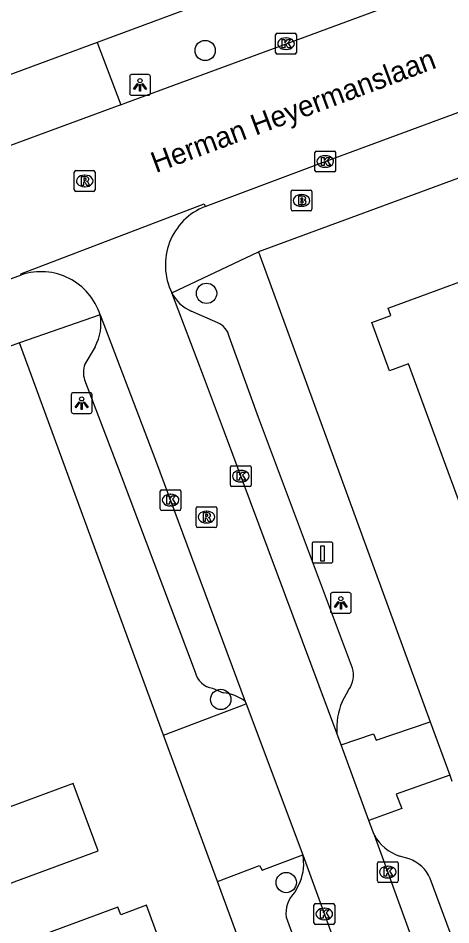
# Model space of a CAD drawing. Extents: x 161258 to 161838, y 380836 to 381727.
# Drawn here: x 161610.91 to 161631.75, y 381428.59 to 381472.25 of the extents above; entities that cross this region are included whole.
import ezdxf

# ---------------------------------------------------------------- set-up
doc = ezdxf.new("R2010")
doc.units = 0
for name, color, linetype in [('IMGEO_Boom', 7, 'Continuous'), ('IMGEO_Brandkraan', 7, 'Continuous'), ('IMGEO_Kolk', 7, 'Continuous'), ('IMGEO_Laadpaal', 7, 'Continuous'), ('IMGEO_Lichtpunt', 7, 'Continuous'), ('IMGEO_Openbare_ruimte_label', 7, 'Continuous'), ('IMGEO_Pand', 7, 'Continuous'), ('IMGEO_Rijbaan_lokaal_open', 7, 'Continuous'), ('IMGEO_Rioolput', 7, 'Continuous'), ('IMGEO_Voetpad_open', 7, 'Continuous')]:
    doc.layers.add(name, color=color, linetype=linetype)

msp = doc.modelspace()

# ---------------------------------------------------------------- linework, layer by layer
at = {"layer": 'IMGEO_Boom'}
for centre in [(161619.92, 381470.692), (161619.985, 381458.999), (161620.669, 381439.444), (161623.822, 381430.63)]:
    msp.add_circle(centre, 0.489, dxfattribs=at)
at = {"layer": 'IMGEO_Brandkraan'}
for p, q in [((161624.136, 381463.971), (161624.988, 381463.971)), ((161624.061, 381463.045), (161624.061, 381463.897)), ((161624.549, 381463.751), (161624.574, 381463.751)), ((161625.062, 381463.897), (161625.062, 381463.045)), ((161624.572, 381463.191), (161624.547, 381463.191)), ((161624.988, 381462.971), (161624.136, 381462.971))]:
    msp.add_line(p, q, dxfattribs=at)
for points in [[(161624.136, 381463.971), (161624.988, 381463.971)], [(161624.061, 381463.045), (161624.061, 381463.897)], [(161624.409, 381463.671), (161624.409, 381463.271), (161624.622, 381463.271)], [(161624.64, 381463.671), (161624.409, 381463.671)], [(161624.588, 381463.59), (161624.534, 381463.59), (161624.534, 381463.514)], [(161624.534, 381463.514), (161624.587, 381463.514)], [(161625.062, 381463.897), (161625.062, 381463.045)], [(161624.596, 381463.438), (161624.534, 381463.438), (161624.534, 381463.357)], [(161624.534, 381463.357), (161624.596, 381463.357)], [(161624.988, 381462.971), (161624.136, 381462.971)]]:
    msp.add_lwpolyline(points, dxfattribs=at)
for centre, radius, start, end in [((161624.138, 381463.895), 0.0765, 91.552, 178.448), ((161624.138, 381463.895), 0.0765, 91.552, 178.448), ((161624.986, 381463.895), 0.0765, 1.552, 88.448), ((161624.986, 381463.895), 0.0765, 1.552, 88.448), ((161624.589, 381463.552), 0.0379, 267.8285, 90.9355), ((161624.644, 381463.526), 0.145, 59.4692, 91.5367), ((161624.669, 381463.573), 0.0922, 285.5137, 58.1501), ((161624.597, 381463.397), 0.0404, 269.8759, 90.5077), ((161624.628, 381463.522), 0.251, 268.6676, 293.5347), ((161624.674, 381463.381), 0.105, 301.3115, 78.989), ((161624.138, 381463.047), 0.0765, 181.552, 268.448), ((161624.138, 381463.047), 0.0765, 181.552, 268.448), ((161624.986, 381463.047), 0.0765, 271.552, 358.448), ((161624.986, 381463.047), 0.0765, 271.552, 358.448)]:
    msp.add_arc(centre, radius, start, end, dxfattribs=at)
for centre, major_axis, ratio, start_param, end_param in [((161624.548, 381463.471), (-0.387, 0.002), 0.722429, 4.712389, 7.853982), ((161624.573, 381463.471), (-0.39, 0.002), 0.717154, 1.570796, 4.712389)]:
    msp.add_ellipse(centre, major_axis=major_axis, ratio=ratio, start_param=start_param, end_param=end_param, dxfattribs=at)
at = {"layer": 'IMGEO_Kolk'}
for p, q in [((161623.313, 381470.594), (161623.313, 381471.446)), ((161623.388, 381471.52), (161624.24, 381471.52)), ((161624.314, 381471.446), (161624.314, 381470.594)), ((161623.801, 381471.3), (161623.826, 381471.3)), ((161624.24, 381470.52), (161623.388, 381470.52)), ((161623.824, 381470.74), (161623.799, 381470.74)), ((161625.202, 381464.921), (161625.202, 381465.773)), ((161625.277, 381465.847), (161626.129, 381465.847)), ((161626.203, 381465.773), (161626.203, 381464.921)), ((161625.69, 381465.627), (161625.715, 381465.627)), ((161626.129, 381464.847), (161625.277, 381464.847)), ((161625.713, 381465.067), (161625.688, 381465.067)), ((161621.133, 381449.77), (161621.133, 381450.622)), ((161621.208, 381450.696), (161622.06, 381450.696)), ((161621.621, 381450.476), (161621.646, 381450.476)), ((161622.134, 381450.622), (161622.134, 381449.77)), ((161617.83, 381449.544), (161618.682, 381449.544)), ((161622.06, 381449.696), (161621.208, 381449.696)), ((161621.644, 381449.916), (161621.619, 381449.916)), ((161617.755, 381448.618), (161617.755, 381449.47)), ((161618.243, 381449.324), (161618.268, 381449.324)), ((161618.756, 381449.47), (161618.756, 381448.618)), ((161618.266, 381448.764), (161618.241, 381448.764)), ((161618.682, 381448.544), (161617.83, 381448.544)), ((161628.285, 381431.633), (161629.137, 381431.633)), ((161628.21, 381430.707), (161628.21, 381431.559)), ((161628.698, 381431.413), (161628.723, 381431.413)), ((161629.211, 381431.559), (161629.211, 381430.707)), ((161628.721, 381430.853), (161628.696, 381430.853)), ((161629.137, 381430.633), (161628.285, 381430.633)), ((161625.156, 381428.69), (161625.156, 381429.542)), ((161625.231, 381429.616), (161626.083, 381429.616)), ((161626.157, 381429.542), (161626.157, 381428.69)), ((161625.644, 381429.396), (161625.669, 381429.396)), ((161626.083, 381428.616), (161625.231, 381428.616)), ((161625.667, 381428.836), (161625.642, 381428.836))]:
    msp.add_line(p, q, dxfattribs=at)
for points in [[(161623.313, 381470.594), (161623.313, 381471.446)], [(161623.388, 381471.52), (161624.24, 381471.52)], [(161624.314, 381471.446), (161624.314, 381470.594)], [(161623.634, 381471.22), (161623.757, 381471.22), (161623.757, 381471.069), (161623.887, 381471.22), (161624.051, 381471.22), (161623.905, 381471.069), (161624.058, 381470.82), (161623.906, 381470.82), (161623.821, 381470.984), (161623.757, 381470.917), (161623.757, 381470.82), (161623.634, 381470.82), (161623.634, 381471.22)], [(161624.24, 381470.52), (161623.388, 381470.52)], [(161625.202, 381464.921), (161625.202, 381465.773)], [(161625.277, 381465.847), (161626.129, 381465.847)], [(161626.203, 381465.773), (161626.203, 381464.921)], [(161625.523, 381465.547), (161625.646, 381465.547), (161625.646, 381465.396), (161625.776, 381465.547), (161625.94, 381465.547), (161625.794, 381465.396), (161625.947, 381465.147), (161625.795, 381465.147), (161625.71, 381465.311), (161625.646, 381465.244), (161625.646, 381465.147), (161625.523, 381465.147), (161625.523, 381465.547)], [(161626.129, 381464.847), (161625.277, 381464.847)], [(161621.133, 381449.77), (161621.133, 381450.622)], [(161621.208, 381450.696), (161622.06, 381450.696)], [(161621.454, 381450.396), (161621.577, 381450.396), (161621.577, 381450.245), (161621.707, 381450.396), (161621.871, 381450.396), (161621.725, 381450.245), (161621.878, 381449.996), (161621.726, 381449.996), (161621.641, 381450.16), (161621.577, 381450.093), (161621.577, 381449.996), (161621.454, 381449.996), (161621.454, 381450.396)], [(161622.134, 381450.622), (161622.134, 381449.77)], [(161617.83, 381449.544), (161618.682, 381449.544)], [(161622.06, 381449.696), (161621.208, 381449.696)], [(161617.755, 381448.618), (161617.755, 381449.47)], [(161618.076, 381449.244), (161618.199, 381449.244), (161618.199, 381449.093), (161618.329, 381449.244), (161618.493, 381449.244), (161618.347, 381449.093), (161618.5, 381448.844), (161618.348, 381448.844), (161618.263, 381449.008), (161618.199, 381448.941), (161618.199, 381448.844), (161618.076, 381448.844), (161618.076, 381449.244)], [(161618.756, 381449.47), (161618.756, 381448.618)], [(161618.682, 381448.544), (161617.83, 381448.544)], [(161628.285, 381431.633), (161629.137, 381431.633)], [(161628.21, 381430.707), (161628.21, 381431.559)], [(161628.531, 381431.333), (161628.654, 381431.333), (161628.654, 381431.182), (161628.784, 381431.333), (161628.948, 381431.333), (161628.802, 381431.182), (161628.955, 381430.933), (161628.803, 381430.933), (161628.718, 381431.097), (161628.654, 381431.03), (161628.654, 381430.933), (161628.531, 381430.933), (161628.531, 381431.333)], [(161629.211, 381431.559), (161629.211, 381430.707)], [(161629.137, 381430.633), (161628.285, 381430.633)], [(161625.156, 381428.69), (161625.156, 381429.542)], [(161625.231, 381429.616), (161626.083, 381429.616)], [(161626.157, 381429.542), (161626.157, 381428.69)], [(161625.477, 381429.316), (161625.6, 381429.316), (161625.6, 381429.165), (161625.73, 381429.316), (161625.894, 381429.316), (161625.748, 381429.165), (161625.901, 381428.916), (161625.749, 381428.916), (161625.664, 381429.08), (161625.6, 381429.013), (161625.6, 381428.916), (161625.477, 381428.916), (161625.477, 381429.316)], [(161626.083, 381428.616), (161625.231, 381428.616)]]:
    msp.add_lwpolyline(points, dxfattribs=at)
for centre, start, end in [((161623.39, 381471.444), 91.552, 178.448), ((161623.39, 381471.444), 91.552, 178.448), ((161624.238, 381471.444), 1.552, 88.448), ((161624.238, 381471.444), 1.552, 88.448), ((161623.39, 381470.596), 181.552, 268.448), ((161623.39, 381470.596), 181.552, 268.448), ((161624.238, 381470.596), 271.552, 358.448), ((161624.238, 381470.596), 271.552, 358.448), ((161625.279, 381465.771), 91.552, 178.448), ((161625.279, 381465.771), 91.552, 178.448), ((161626.127, 381465.771), 1.552, 88.448), ((161626.127, 381465.771), 1.552, 88.448), ((161625.279, 381464.923), 181.552, 268.448), ((161625.279, 381464.923), 181.552, 268.448), ((161626.127, 381464.923), 271.552, 358.448), ((161626.127, 381464.923), 271.552, 358.448), ((161621.21, 381450.62), 91.552, 178.448), ((161621.21, 381450.62), 91.552, 178.448), ((161622.058, 381450.62), 1.552, 88.448), ((161622.058, 381450.62), 1.552, 88.448), ((161617.832, 381449.468), 91.552, 178.448), ((161617.832, 381449.468), 91.552, 178.448), ((161618.68, 381449.468), 1.552, 88.448), ((161618.68, 381449.468), 1.552, 88.448), ((161621.21, 381449.772), 181.552, 268.448), ((161621.21, 381449.772), 181.552, 268.448), ((161622.058, 381449.772), 271.552, 358.448), ((161622.058, 381449.772), 271.552, 358.448), ((161617.832, 381448.62), 181.552, 268.448), ((161617.832, 381448.62), 181.552, 268.448), ((161618.68, 381448.62), 271.552, 358.448), ((161618.68, 381448.62), 271.552, 358.448), ((161628.287, 381431.557), 91.552, 178.448), ((161628.287, 381431.557), 91.552, 178.448), ((161629.135, 381431.557), 1.552, 88.448), ((161629.135, 381431.557), 1.552, 88.448), ((161628.287, 381430.709), 181.552, 268.448), ((161628.287, 381430.709), 181.552, 268.448), ((161629.135, 381430.709), 271.552, 358.448), ((161629.135, 381430.709), 271.552, 358.448), ((161625.233, 381429.54), 91.552, 178.448), ((161625.233, 381429.54), 91.552, 178.448), ((161626.081, 381429.54), 1.552, 88.448), ((161626.081, 381429.54), 1.552, 88.448), ((161625.233, 381428.692), 181.552, 268.448), ((161625.233, 381428.692), 181.552, 268.448), ((161626.081, 381428.692), 271.552, 358.448), ((161626.081, 381428.692), 271.552, 358.448)]:
    msp.add_arc(centre, 0.0765, start, end, dxfattribs=at)
for centre, major_axis, ratio, start_param, end_param in [((161623.8, 381471.02), (-0.387, 0.002), 0.722429, 4.712389, 7.853982), ((161623.825, 381471.02), (-0.39, 0.002), 0.717154, 1.570796, 4.712389), ((161625.689, 381465.347), (-0.387, 0.002), 0.722429, 4.712389, 7.853982), ((161625.714, 381465.347), (-0.39, 0.002), 0.717154, 1.570796, 4.712389), ((161621.62, 381450.196), (-0.387, 0.002), 0.722429, 4.712389, 7.853982), ((161621.645, 381450.196), (-0.39, 0.002), 0.717154, 1.570796, 4.712389), ((161618.242, 381449.044), (-0.387, 0.002), 0.722429, 4.712389, 7.853982), ((161618.267, 381449.044), (-0.39, 0.002), 0.717154, 1.570796, 4.712389), ((161628.697, 381431.133), (-0.387, 0.002), 0.722429, 4.712389, 7.853982), ((161628.722, 381431.133), (-0.39, 0.002), 0.717154, 1.570796, 4.712389), ((161625.643, 381429.116), (-0.387, 0.002), 0.722429, 4.712389, 7.853982), ((161625.668, 381429.116), (-0.39, 0.002), 0.717154, 1.570796, 4.712389)]:
    msp.add_ellipse(centre, major_axis=major_axis, ratio=ratio, start_param=start_param, end_param=end_param, dxfattribs=at)
at = {"layer": 'IMGEO_Laadpaal'}
for p, q in [((161625.069, 381446.938), (161625.069, 381446.097)), ((161625.069, 381446.938), (161625.069, 381446.097)), ((161625.985, 381447.022), (161625.144, 381447.022)), ((161625.985, 381447.022), (161625.144, 381447.022)), ((161626.069, 381446.106), (161626.069, 381446.947)), ((161626.069, 381446.106), (161626.069, 381446.947)), ((161625.153, 381446.022), (161625.994, 381446.022)), ((161625.153, 381446.022), (161625.994, 381446.022))]:
    msp.add_line(p, q, dxfattribs=at)
msp.add_lwpolyline([(161625.484, 381446.835), (161625.644, 381446.835), (161625.644, 381446.102), (161625.484, 381446.102), (161625.484, 381446.835)], dxfattribs=at)
for centre, start, end in [((161625.147, 381446.944), 92.4484, 184.2845), ((161625.147, 381446.944), 92.4484, 184.2845), ((161625.991, 381446.944), 2.4484, 94.2845), ((161625.991, 381446.944), 2.4484, 94.2845), ((161625.147, 381446.1), 182.4484, 274.2845), ((161625.147, 381446.1), 182.4484, 274.2845), ((161625.991, 381446.1), 272.4484, 4.2845), ((161625.991, 381446.1), 272.4484, 4.2845)]:
    msp.add_arc(centre, 0.0779, start, end, dxfattribs=at)
at = {"layer": 'IMGEO_Lichtpunt'}
for p, q in [((161616.285, 381469.441), (161616.285, 381468.634)), ((161616.285, 381469.441), (161616.285, 381468.634)), ((161617.187, 381469.536), (161616.379, 381469.536)), ((161617.187, 381469.536), (161616.379, 381469.536)), ((161617.281, 381468.634), (161617.281, 381469.441)), ((161617.281, 381468.634), (161617.281, 381469.441)), ((161616.379, 381468.54), (161617.187, 381468.54)), ((161616.379, 381468.54), (161617.187, 381468.54)), ((161613.476, 381454.118), (161613.476, 381453.311)), ((161613.476, 381454.118), (161613.476, 381453.311)), ((161614.378, 381454.213), (161613.57, 381454.213)), ((161614.378, 381454.213), (161613.57, 381454.213)), ((161614.472, 381453.311), (161614.472, 381454.118)), ((161614.472, 381453.311), (161614.472, 381454.118)), ((161613.57, 381453.217), (161614.378, 381453.217)), ((161613.57, 381453.217), (161614.378, 381453.217)), ((161625.954, 381444.499), (161625.954, 381443.692)), ((161625.954, 381444.499), (161625.954, 381443.692)), ((161626.856, 381444.594), (161626.048, 381444.594)), ((161626.856, 381444.594), (161626.048, 381444.594)), ((161626.95, 381443.692), (161626.95, 381444.499)), ((161626.95, 381443.692), (161626.95, 381444.499)), ((161626.048, 381443.598), (161626.856, 381443.598)), ((161626.048, 381443.598), (161626.856, 381443.598))]:
    msp.add_line(p, q, dxfattribs=at)
for points in [[(161616.659, 381469.105), (161616.698, 381469.077), (161616.51, 381468.815), (161616.472, 381468.842), (161616.659, 381469.105)], [(161616.761, 381469.057), (161616.808, 381469.057), (161616.808, 381468.735), (161616.761, 381468.735), (161616.761, 381469.057)], [(161616.871, 381469.077), (161616.909, 381469.104), (161617.096, 381468.842), (161617.057, 381468.814), (161616.871, 381469.077)], [(161613.85, 381453.782), (161613.889, 381453.754), (161613.701, 381453.492), (161613.663, 381453.519), (161613.85, 381453.782)], [(161613.952, 381453.734), (161613.999, 381453.734), (161613.999, 381453.412), (161613.952, 381453.412), (161613.952, 381453.734)], [(161614.062, 381453.754), (161614.1, 381453.781), (161614.287, 381453.519), (161614.248, 381453.491), (161614.062, 381453.754)], [(161626.328, 381444.163), (161626.367, 381444.135), (161626.179, 381443.873), (161626.141, 381443.9), (161626.328, 381444.163)], [(161626.43, 381444.115), (161626.477, 381444.115), (161626.477, 381443.793), (161626.43, 381443.793), (161626.43, 381444.115)], [(161626.54, 381444.135), (161626.578, 381444.162), (161626.765, 381443.9), (161626.726, 381443.872), (161626.54, 381444.135)]]:
    msp.add_lwpolyline(points, dxfattribs=at)
for centre in [(161616.784, 381469.239), (161613.975, 381453.916), (161626.453, 381444.297)]:
    msp.add_circle(centre, 0.0994, dxfattribs=at)
for centre, start, end in [((161616.379, 381469.441), 90, 180), ((161616.379, 381469.441), 90, 180), ((161617.187, 381469.441), 0, 90), ((161617.187, 381469.441), 0, 90), ((161616.379, 381468.634), 180, 270), ((161616.379, 381468.634), 180, 270), ((161617.187, 381468.634), 270, 0), ((161617.187, 381468.634), 270, 360), ((161613.57, 381454.118), 90, 180), ((161613.57, 381454.118), 90, 180), ((161614.378, 381454.118), 0, 90), ((161614.378, 381454.118), 0, 90), ((161613.57, 381453.311), 180, 270), ((161613.57, 381453.311), 180, 270), ((161614.378, 381453.311), 270, 0), ((161614.378, 381453.311), 270, 360), ((161626.048, 381444.499), 90, 180), ((161626.048, 381444.499), 90, 180), ((161626.856, 381444.499), 0, 90), ((161626.856, 381444.499), 0, 90), ((161626.048, 381443.692), 180, 270), ((161626.048, 381443.692), 180, 270), ((161626.856, 381443.692), 270, 0), ((161626.856, 381443.692), 270, 360)]:
    msp.add_arc(centre, 0.0946, start, end, dxfattribs=at)
at = {"layer": 'IMGEO_Pand'}
for points in [[(161638.75, 381449.971), (161639.816, 381447.073), (161637.103, 381446.076), (161635.232, 381445.389), (161633.679, 381444.818), (161633.593, 381445.054), (161632.008, 381449.363), (161631.512, 381450.712), (161629.712, 381455.604), (161628.803, 381455.27), (161627.947, 381457.598), (161628.856, 381457.932), (161628.725, 381458.288), (161634.845, 381460.539)], [(161606.966, 381429.283), (161614.764, 381432.159), (161613.568, 381435.402), (161605.743, 381432.515)], [(161618.756, 381423.997), (161617.959, 381426.177), (161618.288, 381426.298), (161617.095, 381429.532), (161615.858, 381429.075), (161615.722, 381429.445), (161611.031, 381427.715), (161607.245, 381426.324), (161608.439, 381423.08), (161607.73, 381422.818), (161607.88, 381422.411), (161606.945, 381422.066), (161607.734, 381419.929), (161609.375, 381420.535)]]:
    msp.add_lwpolyline(points, dxfattribs=at)
at = {"layer": 'IMGEO_Rijbaan_lokaal_open'}
for points in [[(161615.861, 381468.083), (161616.105, 381468.173), (161623.814, 381471.02), (161647.71, 381479.843), (161654.992, 381482.542)], [(161619.919, 381463.183), (161625.703, 381465.347), (161649.734, 381474.239), (161657.089, 381476.959)], [(161615.861, 381468.083), (161607.479, 381464.988)], [(161611.076, 381459.891), (161611.051, 381459.932), (161619.88, 381463.313), (161619.919, 381463.183)], [(161589.036, 381451.805), (161590.467, 381452.331), (161605.602, 381457.905), (161611.076, 381459.891)], [(161626.262, 381437.814), (161620.858, 381452.321), (161619.845, 381455.009), (161618.312, 381459.03)], [(161614.862, 381457.971), (161617.533, 381450.961), (161621.851, 381439.353)], [(161621.851, 381439.353), (161621.897, 381439.229)], [(161621.897, 381439.229), (161624.621, 381431.971)], [(161626.464, 381437.265), (161626.262, 381437.814)], [(161627.799, 381433.622), (161626.464, 381437.265)], [(161628.071, 381432.908), (161628.007, 381433.055), (161627.799, 381433.622)], [(161633.562, 381417.932), (161631.642, 381423.104), (161628.071, 381432.908)], [(161624.621, 381431.971), (161629.58, 381418.332)]]:
    msp.add_lwpolyline(points, dxfattribs=at)
for centre, radius, start, end in [((161621.036, 381460.364), 3.033, 111.605, 206.0871), ((161612.014, 381457.048), 2.994, 17.9573, 108.2607)]:
    msp.add_arc(centre, radius, start, end, dxfattribs=at)
at = {"layer": 'IMGEO_Rioolput'}
for p, q in [((161613.62, 381463.985), (161613.62, 381464.837)), ((161613.695, 381464.911), (161614.547, 381464.911)), ((161614.621, 381464.837), (161614.621, 381463.985)), ((161614.108, 381464.691), (161614.133, 381464.691)), ((161614.131, 381464.131), (161614.106, 381464.131)), ((161614.547, 381463.911), (161613.695, 381463.911)), ((161619.48, 381447.8), (161619.48, 381448.652)), ((161619.555, 381448.726), (161620.407, 381448.726)), ((161620.481, 381448.652), (161620.481, 381447.8)), ((161619.968, 381448.506), (161619.993, 381448.506)), ((161619.991, 381447.946), (161619.966, 381447.946)), ((161620.407, 381447.726), (161619.555, 381447.726))]:
    msp.add_line(p, q, dxfattribs=at)
for points in [[(161613.62, 381463.985), (161613.62, 381464.837)], [(161613.695, 381464.911), (161614.547, 381464.911)], [(161614.621, 381464.837), (161614.621, 381463.985)], [(161614.209, 381464.609), (161613.957, 381464.611), (161613.957, 381464.211)], [(161613.957, 381464.211), (161614.081, 381464.211), (161614.081, 381464.373), (161614.092, 381464.373)], [(161614.135, 381464.53), (161614.081, 381464.53), (161614.081, 381464.449)], [(161614.081, 381464.449), (161614.133, 381464.449)], [(161614.139, 381464.344), (161614.21, 381464.211), (161614.35, 381464.211), (161614.285, 381464.337)], [(161614.547, 381463.911), (161613.695, 381463.911)], [(161619.48, 381447.8), (161619.48, 381448.652)], [(161619.555, 381448.726), (161620.407, 381448.726)], [(161620.481, 381448.652), (161620.481, 381447.8)], [(161620.069, 381448.424), (161619.817, 381448.426), (161619.817, 381448.026)], [(161619.995, 381448.345), (161619.941, 381448.345), (161619.941, 381448.264)], [(161619.941, 381448.264), (161619.993, 381448.264)], [(161619.817, 381448.026), (161619.941, 381448.026), (161619.941, 381448.188), (161619.952, 381448.188)], [(161619.999, 381448.159), (161620.07, 381448.026), (161620.21, 381448.026), (161620.145, 381448.152)], [(161620.407, 381447.726), (161619.555, 381447.726)]]:
    msp.add_lwpolyline(points, dxfattribs=at)
for centre, radius, start, end in [((161613.697, 381464.835), 0.0765, 91.552, 178.448), ((161613.697, 381464.835), 0.0765, 91.552, 178.448), ((161614.545, 381464.835), 0.0765, 1.552, 88.448), ((161614.545, 381464.835), 0.0765, 1.552, 88.448), ((161614.091, 381464.32), 0.0533, 26.0293, 88.6989), ((161614.117, 381464.638), 0.19, 274.7715, 282.9687), ((161614.141, 381464.434), 0.0964, 77.0061, 93.1865), ((161614.155, 381464.491), 0.0378, 276.6634, 79.6772), ((161614.208, 381464.499), 0.109, 350.3612, 89.416), ((161614.206, 381464.499), 0.112, 277.5842, 350.9817), ((161614.19, 381464.284), 0.108, 29.5134, 73.7905), ((161613.697, 381463.987), 0.0765, 181.552, 268.448), ((161613.697, 381463.987), 0.0765, 181.552, 268.448), ((161614.545, 381463.987), 0.0765, 271.552, 358.448), ((161614.545, 381463.987), 0.0765, 271.552, 358.448), ((161619.557, 381448.65), 0.0765, 91.552, 178.448), ((161619.557, 381448.65), 0.0765, 91.552, 178.448), ((161620.405, 381448.65), 0.0765, 1.552, 88.448), ((161620.405, 381448.65), 0.0765, 1.552, 88.448), ((161619.977, 381448.453), 0.19, 274.7715, 282.9687), ((161620.001, 381448.249), 0.0964, 77.0061, 93.1865), ((161620.015, 381448.306), 0.0378, 276.6634, 79.6772), ((161620.068, 381448.314), 0.109, 350.3612, 89.416), ((161620.066, 381448.314), 0.112, 277.5842, 350.9817), ((161619.557, 381447.802), 0.0765, 181.552, 268.448), ((161619.557, 381447.802), 0.0765, 181.552, 268.448), ((161619.951, 381448.135), 0.0533, 26.0293, 88.6989), ((161620.05, 381448.099), 0.108, 29.5134, 73.7905), ((161620.405, 381447.802), 0.0765, 271.552, 358.448), ((161620.405, 381447.802), 0.0765, 271.552, 358.448)]:
    msp.add_arc(centre, radius, start, end, dxfattribs=at)
for centre, major_axis, ratio, start_param, end_param in [((161614.107, 381464.411), (-0.387, 0.002), 0.722429, 4.712389, 7.853982), ((161614.132, 381464.411), (-0.39, 0.002), 0.717154, 1.570796, 4.712389), ((161619.967, 381448.226), (-0.387, 0.002), 0.722429, 4.712389, 7.853982), ((161619.992, 381448.226), (-0.39, 0.002), 0.717154, 1.570796, 4.712389)]:
    msp.add_ellipse(centre, major_axis=major_axis, ratio=ratio, start_param=start_param, end_param=end_param, dxfattribs=at)
at = {"layer": 'IMGEO_Voetpad_open'}
for points in [[(161692.567, 381486.83), (161622.485, 381460.994)], [(161639.66, 381480.333), (161615.03, 381471.197), (161614.726, 381471.084)], [(161614.726, 381471.084), (161606.375, 381467.99)], [(161614.726, 381471.084), (161615.861, 381468.083)], [(161618.312, 381459.03), (161622.485, 381460.994)], [(161622.485, 381460.994), (161630.758, 381438.372)], [(161614.862, 381457.971), (161610.973, 381456.609)], [(161620.526, 381457.581), (161619.253, 381458.145)], [(161610.973, 381456.609), (161591.531, 381449.546), (161590.178, 381449.054)], [(161617.919, 381437.722), (161610.973, 381456.609)], [(161627.01, 381440.954), (161622.485, 381453.014), (161621.083, 381456.914)], [(161614.619, 381456.43), (161614.131, 381455.588)], [(161614.115, 381454.833), (161615.87, 381450.209), (161619.445, 381440.765)], [(161620.279, 381439.987), (161620.786, 381439.77)], [(161626.509, 381439.331), (161626.841, 381439.926)], [(161617.919, 381437.722), (161621.897, 381439.229)], [(161626.464, 381437.265), (161628.026, 381437.789), (161628.152, 381437.484), (161630.758, 381438.372)], [(161630.758, 381438.372), (161631.7, 381435.792)], [(161620.508, 381430.682), (161617.919, 381437.722)], [(161631.7, 381435.792), (161629.12, 381434.891), (161629.396, 381434.192), (161627.799, 381433.622)], [(161631.7, 381435.792), (161631.8, 381435.51)], [(161620.508, 381430.682), (161622.544, 381431.448), (161622.657, 381431.22), (161624.621, 381431.971)], [(161629.742, 381431.766), (161629.273, 381431.907)], [(161635.402, 381418.251), (161630.754, 381430.823)], [(161622.597, 381389.891), (161625.828, 381416.218), (161620.508, 381430.682)], [(161624.496, 381430.667), (161624.24, 381430.16)], [(161623.816, 381428.956), (161626.919, 381420.439)]]:
    msp.add_lwpolyline(points, dxfattribs=at)
for centre, radius, start, end in [((161619.961, 381459.84), 1.837, 206.1701, 247.3432), ((161612.633, 381457.533), 2.272, 330.9599, 11.1177), ((161620.152, 381456.703), 0.954, 12.7837, 66.9457), ((161615.125, 381455.189), 1.071, 158.1398, 199.4321), ((161625.86, 381440.615), 1.199, 324.922, 16.4066), ((161620.41, 381440.963), 0.985, 191.6186, 262.3606), ((161620.52, 381437.523), 2.263, 53.9799, 83.2545), ((161629.628, 381438.045), 3.374, 157.5852, 183.9192), ((161629.94, 381433.93), 2.13, 208.6722, 251.7542), ((161622.38, 381431.528), 2.284, 337.861, 11.1879), ((161629.22, 381430.191), 1.659, 22.38, 71.6627), ((161625.225, 381429.137), 1.42, 133.8951, 187.3045)]:
    msp.add_arc(centre, radius, start, end, dxfattribs=at)

# ---------------------------------------------------------------- texts
at = {"layer": 'IMGEO_Openbare_ruimte_label'}
msp.add_text('Herman Heyermanslaan', height=1, rotation=20.5359, dxfattribs=at).set_placement((161617.543, 381464.789))

doc.saveas('drawing.dxf')
